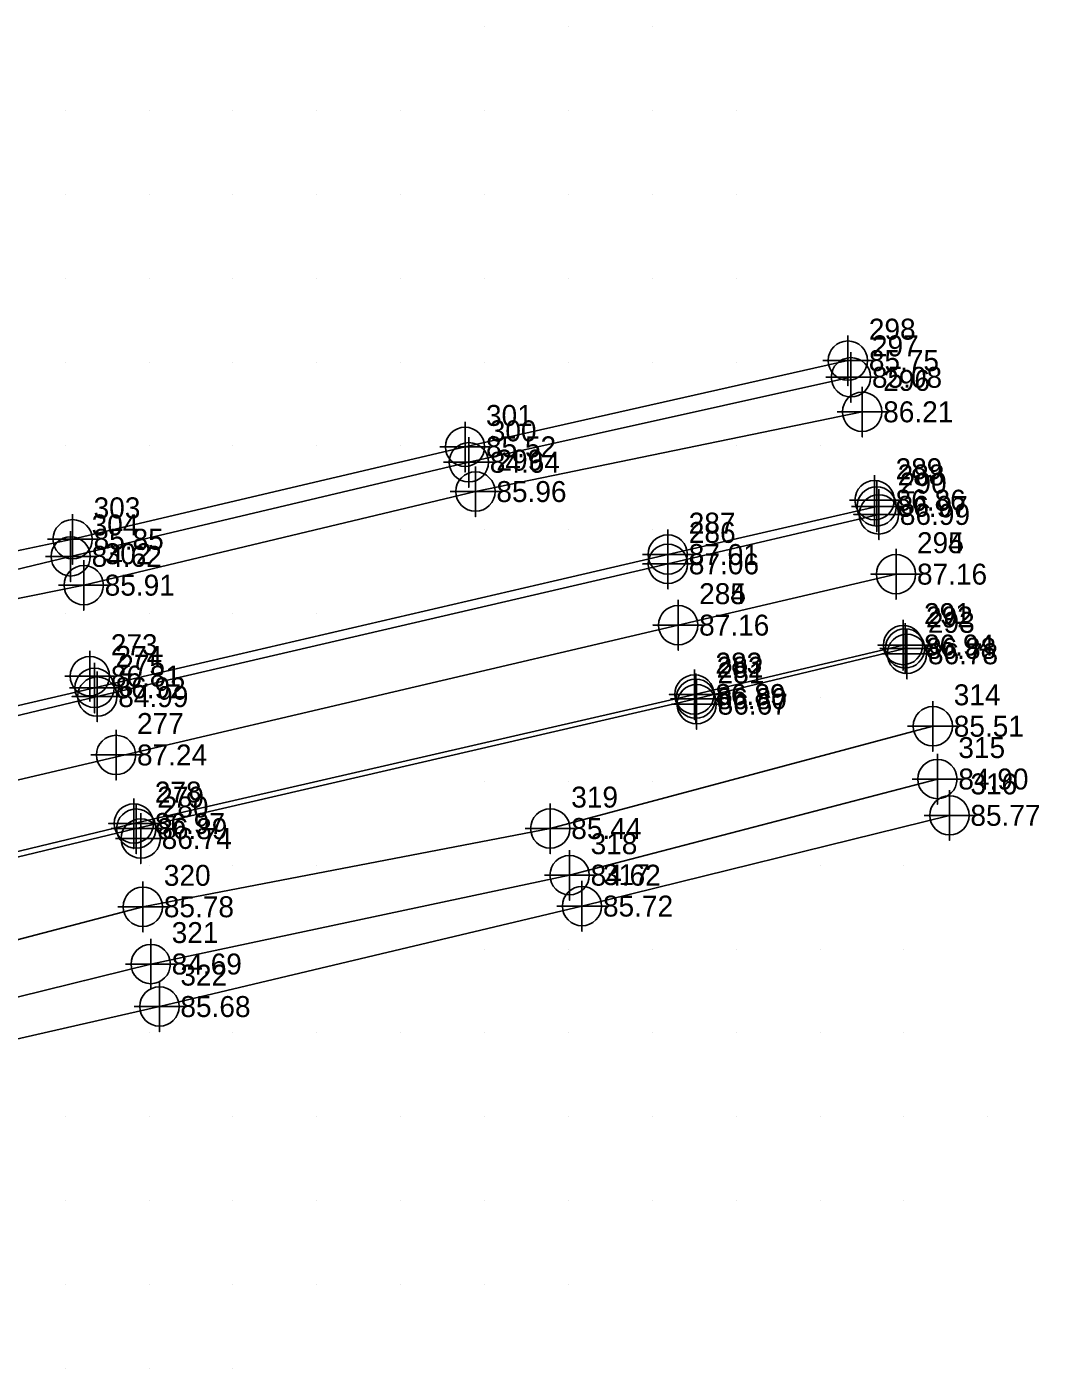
# Model space of a CAD drawing. Extents: x 1988140 to 1988766, y 249950 to 250250.
# Drawn here: x 1988645.4 to 1988766.1, y 250040 to 250200 of the extents above; entities that cross this region are included whole.
import ezdxf

# ---------------------------------------------------------------- set-up
doc = ezdxf.new("R2010")
doc.units = 0
for name, color, linetype in [('Exist DTM Breakline', 7, 'Continuous'), ('Exist DTM Breakline Cogo Elevation', 7, 'Continuous'), ('Exist DTM Breakline Cogo Number', 7, 'Continuous'), ('Exist DTM Breakline Cogo Point CELL', 7, 'Continuous'), ('Exist DTM Crownline', 7, 'Continuous'), ('Exist DTM Crownline Cogo Elevation', 7, 'Continuous'), ('Exist DTM Crownline Cogo Number', 7, 'Continuous'), ('Exist DTM Crownline Cogo Point CELL', 7, 'Continuous'), ('Exist DTM QL2 LIDAR Elevation Point', 7, 'Continuous'), ('Exist DTM Regular Point CELL', 7, 'Continuous'), ('Exist DTM Regular Point Cogo Elevation', 7, 'Continuous'), ('Exist DTM Regular Point Cogo Number', 7, 'Continuous'), ('Exist Roads EOP', 7, 'Continuous'), ('Exist Roads EOP Cogo Elevation', 7, 'Continuous'), ('Exist Roads EOP Cogo Number', 7, 'Continuous'), ('Exist Roads EOP Cogo Point CELL', 7, 'Continuous'), ('Exist Roads EOT', 7, 'Continuous'), ('Exist Roads EOT Cogo Elevation', 7, 'Continuous'), ('Exist Roads EOT Cogo Number', 7, 'Continuous'), ('Exist Roads EOT Cogo Point CELL', 7, 'Continuous')]:
    doc.layers.add(name, color=color, linetype=linetype)

msp = doc.modelspace()

# ---------------------------------------------------------------- linework, layer by layer
at = {"layer": 'Exist DTM Breakline'}
for p, q in [((1988707.8338, 250104.3692), (1988753.4432, 250116.5715)), ((1988595.8486, 250078.4284), (1988659.2567, 250095.0375))]:
    msp.add_line(p, q, dxfattribs=at)
for points in [[(1988555.0044, 250124.5902), (1988568.1239, 250120.6374), (1988600.9717, 250128.3768), (1988650.8805, 250138.872), (1988697.6656, 250149.8966), (1988743.3182, 250160.187)], [(1988555.0333, 250121.6898), (1988567.7596, 250117.9867), (1988601.6281, 250125.0214), (1988650.6465, 250136.8359), (1988698.1189, 250148.056), (1988743.6869, 250158.1958)], [(1988745.028, 250154.0761), (1988698.9071, 250144.5644), (1988652.2033, 250133.4001), (1988602.1386, 250123.2677), (1988568.0707, 250115.6185), (1988551.0253, 250119.1644)], [(1988753.9895, 250110.2756), (1988710.141, 250098.807), (1988660.1934, 250088.2068), (1988597.0615, 250072.5993), (1988550.3151, 250060.6577)], [(1988755.4289, 250105.9435), (1988711.6158, 250095.1192), (1988661.2286, 250083.135)], [(1988707.8338, 250104.3692), (1988659.2567, 250095.0375)], [(1988661.2286, 250083.135), (1988597.985, 250068.7119)]]:
    msp.add_lwpolyline(points, dxfattribs=at)
at = {"layer": 'Exist DTM Breakline Cogo Point CELL'}
for points in [[(1988743.3182, 250163.187), (1988743.3182, 250157.187), (1988743.3182, 250160.187), (1988746.3182, 250160.187), (1988740.3182, 250160.187)], [(1988743.6869, 250161.1958), (1988743.6869, 250155.1958), (1988743.6869, 250158.1958), (1988746.6869, 250158.1958), (1988740.6869, 250158.1958)], [(1988745.028, 250157.0761), (1988745.028, 250151.0761), (1988745.028, 250154.0761), (1988748.028, 250154.0761), (1988742.028, 250154.0761)], [(1988697.6656, 250152.8966), (1988697.6656, 250146.8966), (1988697.6656, 250149.8966), (1988700.6656, 250149.8966), (1988694.6656, 250149.8966)], [(1988698.1189, 250151.056), (1988698.1189, 250145.056), (1988698.1189, 250148.056), (1988701.1189, 250148.056), (1988695.1189, 250148.056)], [(1988698.9071, 250147.5644), (1988698.9071, 250141.5644), (1988698.9071, 250144.5644), (1988701.9071, 250144.5644), (1988695.9071, 250144.5644)], [(1988650.8805, 250141.872), (1988650.8805, 250135.872), (1988650.8805, 250138.872), (1988653.8805, 250138.872), (1988647.8805, 250138.872)], [(1988650.6465, 250139.8359), (1988650.6465, 250133.8359), (1988650.6465, 250136.8359), (1988653.6465, 250136.8359), (1988647.6465, 250136.8359)], [(1988652.2033, 250136.4001), (1988652.2033, 250130.4001), (1988652.2033, 250133.4001), (1988655.2033, 250133.4001), (1988649.2033, 250133.4001)], [(1988753.4432, 250119.5715), (1988753.4432, 250113.5715), (1988753.4432, 250116.5715), (1988756.4432, 250116.5715), (1988750.4432, 250116.5715)], [(1988753.9895, 250113.2756), (1988753.9895, 250107.2756), (1988753.9895, 250110.2756), (1988756.9895, 250110.2756), (1988750.9895, 250110.2756)], [(1988755.4289, 250108.9435), (1988755.4289, 250102.9435), (1988755.4289, 250105.9435), (1988758.4289, 250105.9435), (1988752.4289, 250105.9435)], [(1988707.8338, 250107.3692), (1988707.8338, 250101.3692), (1988707.8338, 250104.3692), (1988710.8338, 250104.3692), (1988704.8338, 250104.3692)], [(1988710.141, 250101.807), (1988710.141, 250095.807), (1988710.141, 250098.807), (1988713.141, 250098.807), (1988707.141, 250098.807)], [(1988659.2567, 250098.0375), (1988659.2567, 250092.0375), (1988659.2567, 250095.0375), (1988662.2567, 250095.0375), (1988656.2567, 250095.0375)], [(1988711.6158, 250098.1192), (1988711.6158, 250092.1192), (1988711.6158, 250095.1192), (1988714.6158, 250095.1192), (1988708.6158, 250095.1192)], [(1988660.1934, 250091.2068), (1988660.1934, 250085.2068), (1988660.1934, 250088.2068), (1988663.1934, 250088.2068), (1988657.1934, 250088.2068)], [(1988661.2286, 250086.135), (1988661.2286, 250080.135), (1988661.2286, 250083.135), (1988664.2286, 250083.135), (1988658.2286, 250083.135)]]:
    msp.add_lwpolyline(points, dxfattribs=at)
for centre in [(1988743.3182, 250160.187), (1988743.6869, 250158.1958), (1988745.028, 250154.0761), (1988697.6656, 250149.8966), (1988698.1189, 250148.056), (1988698.9071, 250144.5644), (1988650.8805, 250138.872), (1988650.6465, 250136.8359), (1988652.2033, 250133.4001), (1988753.4432, 250116.5715), (1988753.9895, 250110.2756), (1988755.4289, 250105.9435), (1988707.8338, 250104.3692), (1988710.141, 250098.807), (1988659.2567, 250095.0375), (1988711.6158, 250095.1192), (1988660.1934, 250088.2068), (1988661.2286, 250083.135)]:
    msp.add_circle(centre, 2.344, dxfattribs=at)
at = {"layer": 'Exist DTM Crownline'}
msp.add_lwpolyline([(1988586.896, 250096.6857), (1988587.4445, 250096.8162), (1988723.0829, 250128.6331), (1988749.0571, 250134.715)], dxfattribs=at)
at = {"layer": 'Exist DTM Crownline Cogo Point CELL'}
for points in [[(1988749.0571, 250137.715), (1988749.0571, 250131.715), (1988749.0571, 250134.715), (1988752.0571, 250134.715), (1988746.0571, 250134.715)], [(1988723.0829, 250131.6331), (1988723.0829, 250125.6331), (1988723.0829, 250128.6331), (1988726.0829, 250128.6331), (1988720.0829, 250128.6331)], [(1988656.0545, 250116.1459), (1988656.0545, 250110.1459), (1988656.0545, 250113.1459), (1988659.0545, 250113.1459), (1988653.0545, 250113.1459)]]:
    msp.add_lwpolyline(points, dxfattribs=at)
for centre in [(1988749.0571, 250134.715), (1988723.0829, 250128.6331), (1988656.0545, 250113.1459)]:
    msp.add_circle(centre, 2.344, dxfattribs=at)
at = {"layer": 'Exist DTM QL2 LIDAR Elevation Point'}
for p, q in [((1988700, 250200), (1988700, 250200)), ((1988710, 250200), (1988710, 250200)), ((1988720, 250200), (1988720, 250200)), ((1988650, 250190), (1988650, 250190)), ((1988660, 250190), (1988660, 250190)), ((1988670, 250190), (1988670, 250190)), ((1988680, 250190), (1988680, 250190)), ((1988690, 250190), (1988690, 250190)), ((1988700, 250190), (1988700, 250190)), ((1988710, 250190), (1988710, 250190)), ((1988720, 250190), (1988720, 250190)), ((1988730, 250190), (1988730, 250190)), ((1988650, 250180), (1988650, 250180)), ((1988660, 250180), (1988660, 250180)), ((1988670, 250180), (1988670, 250180)), ((1988680, 250180), (1988680, 250180)), ((1988690, 250180), (1988690, 250180)), ((1988700, 250180), (1988700, 250180)), ((1988710, 250180), (1988710, 250180)), ((1988720, 250180), (1988720, 250180)), ((1988730, 250180), (1988730, 250180)), ((1988650, 250170), (1988650, 250170)), ((1988660, 250170), (1988660, 250170)), ((1988670, 250170), (1988670, 250170)), ((1988680, 250170), (1988680, 250170)), ((1988690, 250170), (1988690, 250170)), ((1988700, 250170), (1988700, 250170)), ((1988710, 250170), (1988710, 250170)), ((1988720, 250170), (1988720, 250170)), ((1988730, 250170), (1988730, 250170)), ((1988650, 250160), (1988650, 250160)), ((1988660, 250160), (1988660, 250160)), ((1988670, 250160), (1988670, 250160)), ((1988680, 250160), (1988680, 250160)), ((1988690, 250160), (1988690, 250160)), ((1988700, 250160), (1988700, 250160)), ((1988710, 250160), (1988710, 250160)), ((1988720, 250160), (1988720, 250160)), ((1988730, 250160), (1988730, 250160)), ((1988650, 250150), (1988650, 250150)), ((1988660, 250150), (1988660, 250150)), ((1988670, 250150), (1988670, 250150)), ((1988680, 250150), (1988680, 250150)), ((1988690, 250150), (1988690, 250150)), ((1988730, 250150), (1988730, 250150)), ((1988740, 250150), (1988740, 250150)), ((1988690, 250140), (1988690, 250140)), ((1988700, 250140), (1988700, 250140)), ((1988710, 250140), (1988710, 250140)), ((1988720, 250140), (1988720, 250140)), ((1988650, 250130), (1988650, 250130)), ((1988660, 250130), (1988660, 250130)), ((1988670, 250130), (1988670, 250130)), ((1988680, 250130), (1988680, 250130)), ((1988690, 250130), (1988690, 250130)), ((1988740, 250120), (1988740, 250120)), ((1988700, 250110), (1988700, 250110)), ((1988710, 250110), (1988710, 250110)), ((1988720, 250110), (1988720, 250110)), ((1988660, 250100), (1988660, 250100)), ((1988670, 250100), (1988670, 250100)), ((1988680, 250100), (1988680, 250100)), ((1988740, 250100), (1988740, 250100)), ((1988750, 250100), (1988750, 250100)), ((1988700, 250090), (1988700, 250090)), ((1988710, 250090), (1988710, 250090)), ((1988720, 250090), (1988720, 250090)), ((1988730, 250090), (1988730, 250090)), ((1988740, 250090), (1988740, 250090)), ((1988750, 250090), (1988750, 250090)), ((1988660, 250080), (1988660, 250080)), ((1988670, 250080), (1988670, 250080)), ((1988680, 250080), (1988680, 250080)), ((1988690, 250080), (1988690, 250080)), ((1988700, 250080), (1988700, 250080)), ((1988710, 250080), (1988710, 250080)), ((1988720, 250080), (1988720, 250080)), ((1988730, 250080), (1988730, 250080)), ((1988740, 250080), (1988740, 250080)), ((1988750, 250080), (1988750, 250080)), ((1988650, 250070), (1988650, 250070)), ((1988660, 250070), (1988660, 250070)), ((1988670, 250070), (1988670, 250070)), ((1988680, 250070), (1988680, 250070)), ((1988690, 250070), (1988690, 250070)), ((1988700, 250070), (1988700, 250070)), ((1988710, 250070), (1988710, 250070)), ((1988720, 250070), (1988720, 250070)), ((1988730, 250070), (1988730, 250070)), ((1988740, 250070), (1988740, 250070)), ((1988750, 250070), (1988750, 250070)), ((1988760, 250070), (1988760, 250070)), ((1988650, 250060), (1988650, 250060)), ((1988660, 250060), (1988660, 250060)), ((1988670, 250060), (1988670, 250060)), ((1988680, 250060), (1988680, 250060)), ((1988690, 250060), (1988690, 250060)), ((1988700, 250060), (1988700, 250060)), ((1988710, 250060), (1988710, 250060)), ((1988720, 250060), (1988720, 250060)), ((1988730, 250060), (1988730, 250060)), ((1988740, 250060), (1988740, 250060)), ((1988750, 250060), (1988750, 250060)), ((1988650, 250050), (1988650, 250050)), ((1988660, 250050), (1988660, 250050)), ((1988670, 250050), (1988670, 250050)), ((1988680, 250050), (1988680, 250050)), ((1988690, 250050), (1988690, 250050)), ((1988700, 250050), (1988700, 250050)), ((1988710, 250050), (1988710, 250050)), ((1988650, 250040), (1988650, 250040)), ((1988660, 250040), (1988660, 250040)), ((1988670, 250040), (1988670, 250040))]:
    msp.add_line(p, q, dxfattribs=at)
at = {"layer": 'Exist DTM Regular Point CELL'}
for points in [[(1988746.5069, 250146.5369), (1988746.5069, 250140.5369), (1988746.5069, 250143.5369), (1988749.5069, 250143.5369), (1988743.5069, 250143.5369)], [(1988750.3638, 250128.214), (1988750.3638, 250122.214), (1988750.3638, 250125.214), (1988753.3638, 250125.214), (1988747.3638, 250125.214)], [(1988652.9332, 250125.5493), (1988652.9332, 250119.5493), (1988652.9332, 250122.5493), (1988655.9332, 250122.5493), (1988649.9332, 250122.5493)], [(1988725.2854, 250122.2062), (1988725.2854, 250116.2062), (1988725.2854, 250119.2062), (1988728.2854, 250119.2062), (1988722.2854, 250119.2062)], [(1988658.9985, 250106.1878), (1988658.9985, 250100.1878), (1988658.9985, 250103.1878), (1988661.9985, 250103.1878), (1988655.9985, 250103.1878)]]:
    msp.add_lwpolyline(points, dxfattribs=at)
for centre in [(1988746.5069, 250143.5369), (1988750.3638, 250125.214), (1988652.9332, 250122.5493), (1988725.2854, 250119.2062), (1988658.9985, 250103.1878)]:
    msp.add_circle(centre, 2.344, dxfattribs=at)
at = {"layer": 'Exist Roads EOP'}
for points in [[(1988474.5186, 250079.1384), (1988520.6371, 250089.4794), (1988585.1885, 250105.299), (1988653.4927, 250121.1544), (1988721.8388, 250137.0511), (1988746.7518, 250142.7981)], [(1988478.7113, 250061.1525), (1988526.3961, 250072.7689), (1988588.4517, 250087.5135), (1988658.4677, 250104.3569), (1988725.1723, 250119.8591), (1988750.1331, 250125.8579)]]:
    msp.add_lwpolyline(points, dxfattribs=at)
at = {"layer": 'Exist Roads EOP Cogo Point CELL'}
for points in [[(1988746.7518, 250145.7981), (1988746.7518, 250139.7981), (1988746.7518, 250142.7981), (1988749.7518, 250142.7981), (1988743.7518, 250142.7981)], [(1988721.8388, 250140.0511), (1988721.8388, 250134.0511), (1988721.8388, 250137.0511), (1988724.8388, 250137.0511), (1988718.8388, 250137.0511)], [(1988750.1331, 250128.8579), (1988750.1331, 250122.8579), (1988750.1331, 250125.8579), (1988753.1331, 250125.8579), (1988747.1331, 250125.8579)], [(1988653.4927, 250124.1544), (1988653.4927, 250118.1544), (1988653.4927, 250121.1544), (1988656.4927, 250121.1544), (1988650.4927, 250121.1544)], [(1988725.1723, 250122.8591), (1988725.1723, 250116.8591), (1988725.1723, 250119.8591), (1988728.1723, 250119.8591), (1988722.1723, 250119.8591)], [(1988658.4677, 250107.3569), (1988658.4677, 250101.3569), (1988658.4677, 250104.3569), (1988661.4677, 250104.3569), (1988655.4677, 250104.3569)]]:
    msp.add_lwpolyline(points, dxfattribs=at)
for centre in [(1988746.7518, 250142.7981), (1988721.8388, 250137.0511), (1988750.1331, 250125.8579), (1988653.4927, 250121.1544), (1988725.1723, 250119.8591), (1988658.4677, 250104.3569)]:
    msp.add_circle(centre, 2.344, dxfattribs=at)
at = {"layer": 'Exist Roads EOT'}
for points in [[(1988747.017, 250141.8392), (1988721.8571, 250135.9434), (1988653.8188, 250120.1043), (1988585.7363, 250103.7612), (1988520.8576, 250088.4105), (1988474.7146, 250078.1173)], [(1988478.5507, 250062.0221), (1988526.3466, 250073.3488), (1988588.4376, 250088.1415), (1988658.1757, 250104.9714), (1988725.0188, 250120.3526), (1988749.8922, 250126.2558)]]:
    msp.add_lwpolyline(points, dxfattribs=at)
at = {"layer": 'Exist Roads EOT Cogo Point CELL'}
for points in [[(1988747.017, 250144.8392), (1988747.017, 250138.8392), (1988747.017, 250141.8392), (1988744.017, 250141.8392), (1988750.017, 250141.8392)], [(1988721.8571, 250138.9434), (1988721.8571, 250132.9434), (1988721.8571, 250135.9434), (1988718.8571, 250135.9434), (1988724.8571, 250135.9434)], [(1988749.0571, 250137.715), (1988749.0571, 250131.715), (1988749.0571, 250134.715), (1988746.0571, 250134.715), (1988752.0571, 250134.715)], [(1988723.0829, 250131.6331), (1988723.0829, 250125.6331), (1988723.0829, 250128.6331), (1988720.0829, 250128.6331), (1988726.0829, 250128.6331)], [(1988749.8922, 250129.2558), (1988749.8922, 250123.2558), (1988749.8922, 250126.2558), (1988746.8922, 250126.2558), (1988752.8922, 250126.2558)], [(1988725.0188, 250123.3526), (1988725.0188, 250117.3526), (1988725.0188, 250120.3526), (1988722.0188, 250120.3526), (1988728.0188, 250120.3526)], [(1988653.8188, 250123.1043), (1988653.8188, 250117.1043), (1988653.8188, 250120.1043), (1988650.8188, 250120.1043), (1988656.8188, 250120.1043)], [(1988658.1757, 250107.9714), (1988658.1757, 250101.9714), (1988658.1757, 250104.9714), (1988655.1757, 250104.9714), (1988661.1757, 250104.9714)]]:
    msp.add_lwpolyline(points, dxfattribs=at)
for centre in [(1988747.017, 250141.8392), (1988721.8571, 250135.9434), (1988749.0571, 250134.715), (1988723.0829, 250128.6331), (1988749.8922, 250126.2558), (1988653.8188, 250120.1043), (1988725.0188, 250120.3526), (1988658.1757, 250104.9714)]:
    msp.add_circle(centre, 2.344, dxfattribs=at)

# ---------------------------------------------------------------- texts
at = {"layer": 'Exist DTM Breakline Cogo Elevation'}
for s, p in [('85.75', (1988745.8182, 250158.937)), ('85.08', (1988746.1869, 250156.9458)), ('86.21', (1988747.528, 250152.8261)), ('85.52', (1988700.1656, 250148.6466)), ('84.64', (1988700.6189, 250146.806)), ('85.96', (1988701.4071, 250143.3144)), ('85.85', (1988653.3805, 250137.622)), ('84.62', (1988653.1465, 250135.5859)), ('85.91', (1988654.7033, 250132.1501)), ('85.51', (1988755.9432, 250115.3215)), ('84.90', (1988756.4895, 250109.0256)), ('85.77', (1988757.9289, 250104.6935)), ('85.44', (1988710.3338, 250103.1192)), ('84.62', (1988712.641, 250097.557)), ('85.78', (1988661.7567, 250093.7875)), ('85.72', (1988714.1158, 250093.8692)), ('84.69', (1988662.6934, 250086.9568)), ('85.68', (1988663.7286, 250081.885))]:
    msp.add_text(s, height=2.5, dxfattribs=at).set_placement(p)
at = {"layer": 'Exist DTM Breakline Cogo Number'}
for s, p in [('298', (1988745.8182, 250162.687)), ('297', (1988746.1869, 250160.6958)), ('296', (1988747.528, 250156.5761)), ('301', (1988700.1656, 250152.3966)), ('300', (1988700.6189, 250150.556)), ('299', (1988701.4071, 250147.0644)), ('303', (1988653.3805, 250141.372)), ('304', (1988653.1465, 250139.3359)), ('302', (1988654.7033, 250135.9001)), ('314', (1988755.9432, 250119.0715)), ('315', (1988756.4895, 250112.7756)), ('316', (1988757.9289, 250108.4435)), ('319', (1988710.3338, 250106.8692)), ('318', (1988712.641, 250101.307)), ('320', (1988661.7567, 250097.5375)), ('317', (1988714.1158, 250097.6192)), ('321', (1988662.6934, 250090.7068)), ('322', (1988663.7286, 250085.635))]:
    msp.add_text(s, height=2.5, dxfattribs=at).set_placement(p)
at = {"layer": 'Exist DTM Crownline Cogo Elevation'}
for s, p in [('87.16', (1988751.5571, 250133.465)), ('87.16', (1988725.5829, 250127.3831)), ('87.24', (1988658.5545, 250111.8959))]:
    msp.add_text(s, height=2.5, dxfattribs=at).set_placement(p)
at = {"layer": 'Exist DTM Crownline Cogo Number'}
for s, p in [('295', (1988751.5571, 250137.215)), ('285', (1988725.5829, 250131.1331)), ('277', (1988658.5545, 250115.6459))]:
    msp.add_text(s, height=2.5, dxfattribs=at).set_placement(p)
at = {"layer": 'Exist DTM Regular Point Cogo Elevation'}
for s, p in [('86.86', (1988749.0069, 250142.2869)), ('86.78', (1988752.8638, 250123.964)), ('86.81', (1988655.4332, 250121.2993)), ('86.67', (1988727.7854, 250117.9562)), ('86.74', (1988661.4985, 250101.9378))]:
    msp.add_text(s, height=2.5, dxfattribs=at).set_placement(p)
at = {"layer": 'Exist DTM Regular Point Cogo Number'}
for s, p in [('289', (1988749.0069, 250146.0369)), ('293', (1988752.8638, 250127.714)), ('273', (1988655.4332, 250125.0493)), ('281', (1988727.7854, 250121.7062)), ('280', (1988661.4985, 250105.6878))]:
    msp.add_text(s, height=2.5, dxfattribs=at).set_placement(p)
at = {"layer": 'Exist Roads EOP Cogo Elevation'}
for s, p in [('86.97', (1988749.2518, 250141.5481)), ('87.01', (1988724.3388, 250135.8011)), ('86.88', (1988752.6331, 250124.6079)), ('86.92', (1988655.9927, 250119.9044)), ('86.80', (1988727.6723, 250118.6091)), ('86.89', (1988660.9677, 250103.1069))]:
    msp.add_text(s, height=2.5, dxfattribs=at).set_placement(p)
at = {"layer": 'Exist Roads EOP Cogo Number'}
for s, p in [('288', (1988749.2518, 250145.2981)), ('287', (1988724.3388, 250139.5511)), ('292', (1988752.6331, 250128.3579)), ('274', (1988655.9927, 250123.6544)), ('282', (1988727.6723, 250122.3591)), ('279', (1988660.9677, 250106.8569))]:
    msp.add_text(s, height=2.5, dxfattribs=at).set_placement(p)
at = {"layer": 'Exist Roads EOT Cogo Elevation'}
for s, p in [('86.99', (1988749.517, 250140.5892)), ('87.06', (1988724.3571, 250134.6934)), ('87.16', (1988751.5571, 250133.465)), ('87.16', (1988725.5829, 250127.3831)), ('86.94', (1988752.3922, 250125.0058)), ('86.89', (1988727.5188, 250119.1026)), ('84.99', (1988656.3188, 250118.8543)), ('86.97', (1988660.6757, 250103.7214))]:
    msp.add_text(s, height=2.5, dxfattribs=at).set_placement(p)
at = {"layer": 'Exist Roads EOT Cogo Number'}
for s, p in [('290', (1988749.517, 250144.3392)), ('286', (1988724.3571, 250138.4434)), ('294', (1988751.5571, 250137.215)), ('284', (1988725.5829, 250131.1331)), ('291', (1988752.3922, 250128.7558)), ('275', (1988656.3188, 250122.6043)), ('283', (1988727.5188, 250122.8526)), ('278', (1988660.6757, 250107.4714))]:
    msp.add_text(s, height=2.5, dxfattribs=at).set_placement(p)

doc.saveas('drawing.dxf')
